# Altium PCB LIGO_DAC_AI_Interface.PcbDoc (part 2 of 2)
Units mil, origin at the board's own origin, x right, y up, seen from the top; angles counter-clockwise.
Board outline 2600 x 10000 mil, 6 copper layers (Top Layer, InternalPlane1, Mid-Layer 1, Mid-Layer 2, Internal Plane 2, Bottom Layer); 72 components, 113 nets, 425 pads, 169 vias.
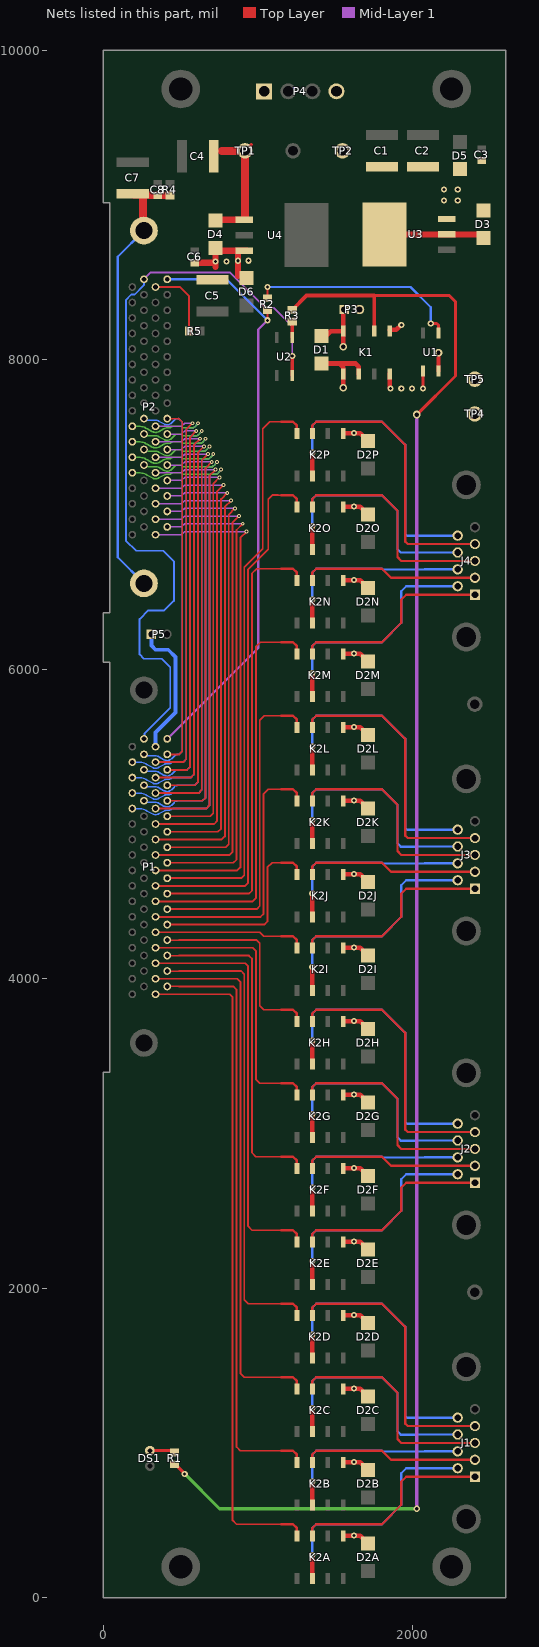
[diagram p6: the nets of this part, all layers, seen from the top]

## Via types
v1: diameter 40, hole 20, Top Layer to Bottom Layer, 134 vias
v2: diameter 25, hole 12, Top Layer to Bottom Layer, 30 vias
v3: diameter 50, hole 28, Top Layer to Bottom Layer, 5 vias

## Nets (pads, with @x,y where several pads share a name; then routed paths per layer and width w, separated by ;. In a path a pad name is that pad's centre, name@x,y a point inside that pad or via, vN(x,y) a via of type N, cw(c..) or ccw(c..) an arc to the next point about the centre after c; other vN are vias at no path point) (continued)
InputN25: P1.59 P2.43 | length 3357.4
  Mid-Layer 2 w8: v2@760,7287.52 v2(760,7290)
  Mid-Layer 2 w9: P2.43@186.81,7270 224.74,7270 226.94,7270 cw(c226.94,7164.19) 283.01,7253.92 283.21,7253.81 315.61,7236.08 ccw(c336.81,7270) 336.81,7230 ccw(c336.81,7270) 358.01,7236.08 390.61,7253.92 cw(c411.81,7220) 411.81,7260 424.74,7260 ccw(c424.74,7277.07) 436.81,7265 cw(c448.88,7252.93) 448.88,7270 486.81,7270 505,7270
  Mid-Layer 2 w10: 505,7270 515,7260 727.28,7260 ccw(c727.28,7270) 732.64,7261.55 735.28,7263.23 741.74,7268.19 ccw(c725,7290) 748.39,7275.54 cw(c756.89,7270.27) 749.79,7277.31 758.25,7285.77 ccw(c754.02,7290) v2(760,7290)
  Bottom Layer w8: v2@760,7287.52 v2(760,7290)
  Bottom Layer w9: P1.59@186.81,5100 224.74,5100 226.94,5100 cw(c226.94,4994.19) 283.01,5083.92 283.21,5083.81 315.61,5066.08 ccw(c336.81,5100) 336.81,5060 ccw(c336.81,5100) 358.01,5066.08 390.61,5083.92 cw(c411.81,5050) 411.81,5090 424.74,5090 ccw(c424.74,5107.07) 436.81,5095 cw(c448.88,5082.93) 448.88,5100
  Bottom Layer w10: 695,7260 727.28,7260 ccw(c727.28,7270) 732.64,7261.55 735.28,7263.23 741.74,7268.19 ccw(c725,7290) 748.39,7275.54 cw(c756.89,7270.27) 749.79,7277.31 758.25,7285.77 ccw(c754.02,7290) v2(760,7290)
  Bottom Layer w12: 448.88,5100 665,5100 685,5120 685,7246.81 ; 685,7250 695,7260
InputN26: P1.60 P2.44 | length 3166.4
  Mid-Layer 2 w8: v2@735,7337.52 v2(735,7340)
  Mid-Layer 2 w9: P2.44@261.81,7320 ccw(c285.95,7344.14) 285.95,7310 336.81,7310 cw(c336.81,7270) 358.01,7303.92 390.61,7286.08 ccw(c411.81,7320) 411.81,7280 ccw(c411.81,7320) 440.1,7291.72 440.1,7291.92 456.46,7308.28 cw(c484.74,7280) 484.74,7320 486.81,7320 505,7320
  Mid-Layer 2 w10: 505,7320 515,7310 702.28,7310 ccw(c702.28,7320) 707.64,7311.55 710.28,7313.23 716.74,7318.19 ccw(c700,7340) 723.39,7325.54 cw(c731.89,7320.27) 724.79,7327.31 733.25,7335.77 ccw(c729.02,7340) v2(735,7340)
  Bottom Layer w8: v2@735,7337.52 v2(735,7340)
  Bottom Layer w9: P1.60@261.81,5150 ccw(c285.95,5174.14) 285.95,5140 336.81,5140 cw(c336.81,5100) 358.01,5133.92 390.61,5116.08 ccw(c411.81,5150) 411.81,5110 ccw(c411.81,5150) 440.1,5121.72 440.1,5121.92 456.46,5138.28 cw(c484.74,5110) 484.74,5150
  Bottom Layer w10: 670,7310 702.28,7310 ccw(c702.28,7320) 707.64,7311.55 710.28,7313.23 716.74,7318.19 ccw(c700,7340) 723.39,7325.54 cw(c731.89,7320.27) 724.79,7327.31 733.25,7335.77 ccw(c729.02,7340) v2(735,7340)
  Bottom Layer w12: 484.74,5150 640,5150 660,5170 660,7296.81 ; 660,7300 670,7310
InputN27: P1.61 P2.45 | length 3257.4
  Mid-Layer 2 w8: v2@710,7387.52 v2(710,7390)
  Mid-Layer 2 w9: P2.45@186.81,7370 224.74,7370 226.94,7370 cw(c226.94,7264.19) 283.01,7353.92 283.21,7353.81 315.61,7336.08 ccw(c336.81,7370) 336.81,7330 ccw(c336.81,7370) 358.01,7336.08 390.61,7353.92 cw(c411.81,7320) 411.81,7360 424.74,7360 ccw(c424.74,7377.07) 436.81,7365 cw(c448.88,7352.93) 448.88,7370 486.81,7370 505,7370
  Mid-Layer 2 w10: 505,7370 515,7360 677.28,7360 ccw(c677.28,7370) 682.64,7361.55 685.28,7363.23 691.74,7368.19 ccw(c675,7390) 698.39,7375.54 cw(c706.89,7370.27) 699.79,7377.31 708.25,7385.77 ccw(c704.02,7390) v2(710,7390)
  Bottom Layer w8: v2@710,7387.52 v2(710,7390)
  Bottom Layer w9: P1.61@186.81,5200 224.74,5200 226.94,5200 cw(c226.94,5094.19) 283.01,5183.92 283.21,5183.81 315.61,5166.08 ccw(c336.81,5200) 336.81,5160 ccw(c336.81,5200) 358.01,5166.08 390.61,5183.92 cw(c411.81,5150) 411.81,5190 424.74,5190 ccw(c424.74,5207.07) 436.81,5195 cw(c448.88,5182.93) 448.88,5200
  Bottom Layer w10: 645,7360 677.28,7360 ccw(c677.28,7370) 682.64,7361.55 685.28,7363.23 691.74,7368.19 ccw(c675,7390) 698.39,7375.54 cw(c706.89,7370.27) 699.79,7377.31 708.25,7385.77 ccw(c704.02,7390) v2(710,7390)
  Bottom Layer w12: 448.88,5200 615,5200 635,5220 635,7346.81 ; 635,7350 645,7360
InputN28: P1.62 P2.46 | length 3066.4
  Mid-Layer 2 w8: v2@685,7437.52 v2(685,7440)
  Mid-Layer 2 w9: P2.46@261.81,7420 ccw(c285.95,7444.14) 285.95,7410 336.81,7410 cw(c336.81,7370) 358.01,7403.92 390.61,7386.08 ccw(c411.81,7420) 411.81,7380 ccw(c411.81,7420) 440.1,7391.72 440.1,7391.92 456.46,7408.28 cw(c484.74,7380) 484.74,7420 486.81,7420 505,7420
  Mid-Layer 2 w10: 505,7420 515,7410 652.28,7410 ccw(c652.28,7420) 657.64,7411.55 660.28,7413.23 666.74,7418.19 ccw(c650,7440) 673.39,7425.54 cw(c681.89,7420.27) 674.79,7427.31 683.25,7435.77 ccw(c679.02,7440) v2(685,7440)
  Bottom Layer w8: v2@685,7437.52 v2(685,7440)
  Bottom Layer w9: P1.62@261.81,5250 ccw(c285.95,5274.14) 285.95,5240 336.81,5240 cw(c336.81,5200) 358.01,5233.92 390.61,5216.08 ccw(c411.81,5250) 411.81,5210 ccw(c411.81,5250) 440.1,5221.72 440.1,5221.92 456.46,5238.28 cw(c484.74,5210) 484.74,5250
  Bottom Layer w10: 620,7410 652.28,7410 ccw(c652.28,7420) 657.64,7411.55 660.28,7413.23 666.74,7418.19 ccw(c650,7440) 673.39,7425.54 cw(c681.89,7420.27) 674.79,7427.31 683.25,7435.77 ccw(c679.02,7440) v2(685,7440)
  Bottom Layer w12: 484.74,5250 590,5250 610,5270 610,7396.81 ; 610,7400 620,7410
InputN29: P1.63 P2.47 | length 3157.4
  Mid-Layer 2 w8: v2@660,7487.52 v2(660,7490)
  Mid-Layer 2 w9: P2.47@186.81,7470 224.74,7470 226.94,7470 cw(c226.94,7364.19) 283.01,7453.92 283.21,7453.81 315.61,7436.08 ccw(c336.81,7470) 336.81,7430 ccw(c336.81,7470) 358.01,7436.08 390.61,7453.92 cw(c411.81,7420) 411.81,7460 424.74,7460 ccw(c424.74,7477.07) 436.81,7465 cw(c448.88,7452.93) 448.88,7470 486.81,7470 505,7470
  Mid-Layer 2 w10: 505,7470 515,7460 627.28,7460 ccw(c627.28,7470) 632.64,7461.55 635.28,7463.23 641.74,7468.19 ccw(c625,7490) 648.39,7475.54 cw(c656.89,7470.27) 649.79,7477.31 658.25,7485.77 ccw(c654.02,7490) v2(660,7490)
  Bottom Layer w8: v2@660,7487.52 v2(660,7490)
  Bottom Layer w9: P1.63@186.81,5300 224.74,5300 226.94,5300 cw(c226.94,5194.19) 283.01,5283.92 283.21,5283.81 315.61,5266.08 ccw(c336.81,5300) 336.81,5260 ccw(c336.81,5300) 358.01,5266.08 390.61,5283.92 cw(c411.81,5250) 411.81,5290 424.74,5290 ccw(c424.74,5307.07) 436.81,5295 cw(c448.88,5282.93) 448.88,5300
  Bottom Layer w10: 595,7460 627.28,7460 ccw(c627.28,7470) 632.64,7461.55 635.28,7463.23 641.74,7468.19 ccw(c625,7490) 648.39,7475.54 cw(c656.89,7470.27) 649.79,7477.31 658.25,7485.77 ccw(c654.02,7490) v2(660,7490)
  Bottom Layer w12: 448.88,5300 565,5300 585,5320 585,7446.81 ; 585,7450 595,7460
InputN30: P1.64 P2.48 | length 2969.6
  Mid-Layer 2 w8: v2@635,7537.52 v2(635,7540)
  Mid-Layer 2 w9: P2.48@261.81,7520 ccw(c285.95,7544.14) 285.95,7510 336.81,7510 cw(c336.81,7470) 358.01,7503.92 390.61,7486.08 ccw(c411.81,7520) 411.81,7480 ccw(c411.81,7520) 440.1,7491.72 440.1,7491.92 456.46,7508.28 cw(c484.74,7480) 484.74,7520 486.81,7520 505,7520
  Mid-Layer 2 w10: 505,7520 515,7510 602.28,7510 ccw(c602.28,7520) 607.64,7511.55 610.28,7513.23 616.74,7518.19 ccw(c600,7540) 623.39,7525.54 cw(c631.89,7520.27) 624.79,7527.31 633.25,7535.77 ccw(c629.02,7540) v2(635,7540)
  Bottom Layer w8: v2@635,7537.52 v2(635,7540)
  Bottom Layer w9: P1.64@261.81,5350 ccw(c285.95,5374.14) 285.95,5340 336.81,5340 cw(c336.81,5300) 358.01,5333.92 390.61,5316.08 ccw(c411.81,5350) 411.81,5310 ccw(c411.81,5350) 440.1,5321.72 440.1,5321.92 456.46,5338.28 cw(c484.74,5310) 484.74,5350
  Bottom Layer w10: 570,7510 602.28,7510 ccw(c602.28,7520) 607.64,7511.55 610.28,7513.23 616.74,7518.19 ccw(c600,7540) 623.39,7525.54 cw(c631.89,7520.27) 624.79,7527.31 633.25,7535.77 ccw(c629.02,7540) v2(635,7540)
  Bottom Layer w12: 484.74,5350 540,5350 560,5370 560,7500 570,7510
InputN31: P1.65 P2.49 | length 3083.2
  Mid-Layer 2 w8: v2@610,7587.52 v2(610,7590)
  Mid-Layer 2 w9: P2.49@186.81,7570 224.74,7570 226.94,7570 cw(c226.94,7464.19) 283.01,7553.92 283.21,7553.81 315.61,7536.08 ccw(c336.81,7570) 336.81,7530 ccw(c336.81,7570) 358.01,7536.08 390.61,7553.92 cw(c411.81,7520) 411.81,7560 424.74,7560 ccw(c424.74,7577.07) 436.81,7565 cw(c448.88,7552.93) 448.88,7570 486.81,7570 505,7570
  Mid-Layer 2 w10: 505,7570 515,7560 577.28,7560 ; 577.28,7560 ccw(c577.28,7570) 582.64,7561.55 ; 577.28,7560 ccw(c577.28,7570) 582.64,7561.55 ; 582.64,7561.55 585.28,7563.23 591.74,7568.19 ; 591.74,7568.19 ccw(c575,7590) 598.39,7575.54 ; 591.74,7568.19 ccw(c575,7590) 598.39,7575.54 ; 598.39,7575.54 cw(c606.89,7570.27) 599.79,7577.31 ; 598.39,7575.54 cw(c606.89,7570.27) 599.79,7577.31 ; 599.79,7577.31 v2@608.25,7585.77 ; v2@608.25,7585.77 ccw(c604.02,7590) v2(610,7590) cw(c604.02,7590) v2@608.25,7585.77
  Bottom Layer w8: v2@610,7587.52 v2(610,7590)
  Bottom Layer w9: P1.65@186.81,5400 224.74,5400 226.94,5400 cw(c226.94,5294.19) 283.01,5383.92 283.21,5383.81 315.61,5366.08 ccw(c336.81,5400) 336.81,5360 ccw(c336.81,5400) 358.01,5366.08 390.61,5383.92 cw(c411.81,5350) 411.81,5390 424.74,5390 ccw(c424.74,5407.07) 436.81,5395 cw(c448.88,5382.93) 448.88,5400
  Bottom Layer w10: 545,7560 577.28,7560 ccw(c577.28,7570) 582.64,7561.55 585.28,7563.23 591.74,7568.19 ccw(c575,7590) 598.39,7575.54 cw(c606.89,7570.27) 599.79,7577.31 608.25,7585.77 ccw(c604.02,7590) v2(610,7590)
  Bottom Layer w12: 448.88,5400 515,5400 535,5420 535,7550 545,7560
InputN32: P1.66 P2.50 | length 2682.6
  Bottom Layer w9: P1.66@261.81,5450 ccw(c285.95,5474.14) 285.95,5440 336.81,5440 cw(c336.81,5400) 358.01,5433.92 390.61,5416.08 ccw(c411.81,5450) 411.81,5410 ccw(c411.81,5450) 440.1,5421.72 440.1,5421.92 456.46,5438.28 cw(c484.74,5410) 484.74,5450 486.81,5450 ; P2.50@261.81,7620 ccw(c285.95,7644.14) 285.95,7610 336.81,7610 cw(c336.81,7570) 358.01,7603.92 390.61,7586.08 ccw(c411.81,7620) 411.81,7580 ccw(c411.81,7620) 440.1,7591.72 440.1,7591.92 456.46,7608.28 cw(c484.74,7580) 484.74,7620 486.81,7620
  Bottom Layer w12: 486.81,7620 509,7597.81 509,5469 490,5450
InputP1: K2A.4 P1.1 | length 4372.2
  Top Layer w9: P1.1@336.81,3900 486.81,3900
  Top Layer w12: 486.81,3900 815,3900 835,3880 835,500 860,475 1130,475 1150,475
  Top Layer w15: 1150,475 1225,475 1250,450 K2A.4@1250,400
InputP2: K2B.4 P1.2 | length 3872.2
  Top Layer w9: P1.2@411.81,3950 486.81,3950
  Top Layer w12: 486.81,3950 840,3950 860,3930 860,975 885,950 1130,950 1150,950
  Top Layer w15: 1150,950 1225,950 1250,925 K2B.4@1250,875
InputP3: K2C.4 P1.3 | length 3522.2
  Top Layer w9: P1.3@336.81,4000 486.81,4000
  Top Layer w12: 486.81,4000 865,4000 885,3980 885,1450 910,1425 1130,1425 1150,1425
  Top Layer w15: 1150,1425 1225,1425 1250,1400 K2C.4@1250,1350
InputP4: K2D.4 P1.4 | length 3022.2
  Top Layer w9: P1.4@411.81,4050 486.81,4050
  Top Layer w12: 486.81,4050 890,4050 910,4030 910,1925 935,1900 1130,1900 1150,1900
  Top Layer w15: 1150,1900 1225,1900 1250,1875 K2D.4@1250,1825
InputP5: K2E.4 P1.5 | length 2672.2
  Top Layer w9: P1.5@336.81,4100 486.81,4100
  Top Layer w12: 486.81,4100 915,4100 935,4080 935,2400 960,2375 1130,2375 1150,2375
  Top Layer w15: 1150,2375 1225,2375 1250,2350 K2E.4@1250,2300
InputP6: K2F.4 P1.6 | length 2172.2
  Top Layer w9: P1.6@411.81,4150 486.81,4150
  Top Layer w12: 486.81,4150 940,4150 960,4130 960,2875 985,2850 1130,2850 1150,2850
  Top Layer w15: 1150,2850 1225,2850 1250,2825 K2F.4@1250,2775
InputP7: K2G.4 P1.7 | length 1822.2
  Top Layer w9: P1.7@336.81,4200 486.81,4200
  Top Layer w12: 486.81,4200 965,4200 985,4180 985,3350 1010,3325 1130,3325 1150,3325
  Top Layer w15: 1150,3325 1225,3325 1250,3300 K2G.4@1250,3250
InputP8: K2H.4 P1.8 | length 1322.2
  Top Layer w9: P1.8@411.81,4250 486.81,4250
  Top Layer w12: 486.81,4250 990,4250 1010,4230 1010,3825 1035,3800 1130,3800 1150,3800
  Top Layer w15: 1150,3800 1225,3800 1250,3775 K2H.4@1250,3725
InputP9: K2I.4 P1.9 | length 983.9
  Top Layer w12: P1.9@336.81,4300 1010,4300 1035,4275 1130,4275 1150,4275
  Top Layer w15: 1150,4275 1225,4275 1250,4250 K2I.4@1250,4200
InputP10: K2J.4 P1.10 | length 1269.3
  Top Layer w12: P1.10@411.81,4350 1040,4350 1060,4370 1060,4720 1090,4750 1130,4750 1150,4750
  Top Layer w15: 1150,4750 1225,4750 1250,4725 K2J.4@1250,4675
InputP11: K2K.4 P1.11 | length 1769.3
  Top Layer w12: P1.11@336.81,4400 1015,4400 1035,4420 1035,5195 1065,5225 1130,5225 1150,5225
  Top Layer w15: 1150,5225 1225,5225 1250,5200 K2K.4@1250,5150
InputP12: K2L.4 P1.12 | length 2119.3
  Top Layer w12: P1.12@411.81,4450 990,4450 1010,4470 1010,5670 1040,5700 1130,5700 1150,5700
  Top Layer w15: 1150,5700 1225,5700 1250,5675 K2L.4@1250,5625
InputP13: K2M.4 P1.13 | length 2619.3
  Top Layer w12: P1.13@336.81,4500 965,4500 985,4520 985,6145 1015,6175 1130,6175 1150,6175
  Top Layer w15: 1150,6175 1225,6175 1250,6150 K2M.4@1250,6100
InputP14: K2N.4 P1.14 | length 2969.3
  Top Layer w12: P1.14@411.81,4550 940,4550 960,4570 960,6620 990,6650 1130,6650 1150,6650
  Top Layer w15: 1150,6650 1225,6650 1250,6625 K2N.4@1250,6575
InputP15: K2O.4 P1.15 | length 3396.4
  Top Layer w12: P1.15@336.81,4600 915,4600 935,4620 935,6645 1065,6775 1065,7100 1090.79,7125.79 1130,7125.79 1150,7125
  Top Layer w15: 1150,7125 1225,7125 1250,7100 K2O.4@1250,7050
InputP16: K2P.4 P1.16 | length 3740.2
  Top Layer w12: P1.16@411.81,4650 890,4650 910,4670 910,6660 1030,6780 1030,7555 1075,7600 1130,7600 1150,7600
  Top Layer w15: 1150,7600 1225,7600 1250,7575 K2P.4@1250,7525
InputP17: P1.17 P2.1 | length 3336.3
  Top Layer w12: P1.17@336.81,4700 865,4700 885,4720 885,6846.81 ; 885,6850 v2(925,6890)
  Mid-Layer 1 w9: P2.1@336.81,6870 486.81,6870 505,6870
  Mid-Layer 1 w10: 505,6870 525,6890 v2(925,6890)
InputP18: P1.18 P2.2 | length 3136.3
  Top Layer w12: P1.18@411.81,4750 840,4750 860,4770 860,6896.81 ; 860,6900 v2(900,6940)
  Mid-Layer 1 w9: P2.2@411.81,6920 486.81,6920 505,6920
  Mid-Layer 1 w10: 505,6920 525,6940 v2(900,6940)
InputP19: P1.19 P2.3 | length 3236.3
  Top Layer w12: P1.19@336.81,4800 815,4800 835,4820 835,6946.81 ; 835,6950 v2(875,6990)
  Mid-Layer 1 w9: P2.3@336.81,6970 486.81,6970 505,6970
  Mid-Layer 1 w10: 505,6970 525,6990 v2(875,6990)
InputP20: P1.20 P2.4 | length 3036.3
  Top Layer w12: P1.20@411.81,4850 790,4850 810,4870 810,6996.81 ; 810,7000 v2(850,7040)
  Mid-Layer 1 w9: P2.4@411.81,7020 486.81,7020 505,7020
  Mid-Layer 1 w10: 505,7020 525,7040 v2(850,7040)
InputP21: P1.21 P2.5 | length 3136.3
  Top Layer w12: P1.21@336.81,4900 765,4900 785,4920 785,7046.81 ; 785,7050 v2(825,7090)
  Mid-Layer 1 w9: P2.5@336.81,7070 486.81,7070 505,7070
  Mid-Layer 1 w10: 505,7070 525,7090 v2(825,7090)
InputP22: P1.22 P2.6 | length 2936.3
  Top Layer w12: P1.22@411.81,4950 740,4950 760,4970 760,7096.81 ; 760,7100 v2(800,7140)
  Mid-Layer 1 w9: P2.6@411.81,7120 486.81,7120 505,7120
  Mid-Layer 1 w10: 505,7120 525,7140 v2(800,7140)
InputP23: P1.23 P2.7 | length 3036.3
  Top Layer w12: P1.23@336.81,5000 715,5000 735,5020 735,7146.81 ; 735,7150 v2(775,7190)
  Mid-Layer 1 w9: P2.7@336.81,7170 486.81,7170 505,7170
  Mid-Layer 1 w10: 505,7170 525,7190 v2(775,7190)
InputP24: P1.24 P2.8 | length 2836.3
  Top Layer w12: P1.24@411.81,5050 690,5050 710,5070 710,7196.81 ; 710,7200 v2(750,7240)
  Mid-Layer 1 w9: P2.8@411.81,7220 486.81,7220 505,7220
  Mid-Layer 1 w10: 505,7220 525,7240 v2(750,7240)
InputP25: P1.25 P2.9 | length 2936.3
  Top Layer w12: P1.25@336.81,5100 665,5100 685,5120 685,7246.81 ; 685,7250 v2(725,7290)
  Mid-Layer 1 w9: P2.9@336.81,7270 486.81,7270 505,7270
  Mid-Layer 1 w10: 505,7270 525,7290 v2(725,7290)
InputP26: P1.26 P2.10 | length 2736.3
  Top Layer w12: P1.26@411.81,5150 640,5150 660,5170 660,7296.81 ; 660,7300 v2(700,7340)
  Mid-Layer 1 w9: P2.10@411.81,7320 486.81,7320 505,7320
  Mid-Layer 1 w10: 505,7320 525,7340 v2(700,7340)
InputP27: P1.27 P2.11 | length 2836.3
  Top Layer w12: P1.27@336.81,5200 615,5200 635,5220 635,7346.81 ; 635,7350 v2(675,7390)
  Mid-Layer 1 w9: P2.11@336.81,7370 486.81,7370 505,7370
  Mid-Layer 1 w10: 505,7370 525,7390 v2(675,7390)
InputP28: P1.28 P2.12 | length 2636.3
  Top Layer w12: P1.28@411.81,5250 590,5250 610,5270 610,7396.81 ; 610,7400 v2(650,7440)
  Mid-Layer 1 w9: P2.12@411.81,7420 486.81,7420 505,7420
  Mid-Layer 1 w10: 505,7420 525,7440 v2(650,7440)
InputP29: P1.29 P2.13 | length 2736.3
  Top Layer w12: P1.29@336.81,5300 565,5300 585,5320 585,7446.81 ; 585,7450 v2(625,7490)
  Mid-Layer 1 w9: P2.13@336.81,7470 486.81,7470 505,7470
  Mid-Layer 1 w10: 505,7470 525,7490 v2(625,7490)
InputP30: P1.30 P2.14 | length 2539.5
  Top Layer w12: P1.30@411.81,5350 540,5350 560,5370 560,7500 v2(600,7540)
  Mid-Layer 1 w9: P2.14@411.81,7520 486.81,7520 505,7520
  Mid-Layer 1 w10: 505,7520 525,7540 v2(600,7540)
InputP31: P1.31 P2.15 | length 2639.5
  Top Layer w12: P1.31@336.81,5400 515,5400 535,5420 535,7550 v2(575,7590)
  Mid-Layer 1 w9: P2.15@336.81,7570 486.81,7570 505,7570
  Mid-Layer 1 w10: 505,7570 525,7590 v2(575,7590)
InputP32: P1.32 P2.16 | length 2340.3
  Top Layer w9: P2.16@411.81,7620 486.81,7620
  Top Layer w12: P1.32@411.81,5450 490,5450 509,5469 509,7597.81 486.81,7620
InputRTN: P1.33 P5.1 | length 891.8
  Bottom Layer w25: P5.1@310,6226.5 310,6153 337,6126 419,6126 465,6080 465,5720 336.81,5591.81 P1.33@336.81,5500
NetC7_2: C7.2 C8.2 P2.69 P2.70 R4.1 | length 2869.6
  Top Layer w25: P2.70@255,8841.77 P2.70@261.81,8834.96
  Top Layer w50: C7.2@196.5,9066.14 255,9066.14 295.08,9066.14 298.62,9062.6 345,9062.6 R4.1@425,9062.6 ; P2.70@255,8841.77 C7.2@255,9051.54
  Bottom Layer w15: P2.69@261.81,6555.04 92.5,6724.35 92.5,8665.65 P2.70@261.81,8834.96
NetD1_1: D1.1 K1.8 P3.1 U1.4 | length 496
  Top Layer w25: U1.4@2165,7926.97 v3(2165,8045)
  Top Layer w30: D1.1@1410,8153.58 1438.58,8153.58 1470,8185 K1.8@1550,8185 ; v3(1550,8085) K1.8@1550,8185 ; P3.1@1550,8310 K1.8@1550,8185
NetDS1_2: DS1.2 R1.1 | length 154.9
  Top Layer w20: DS1.2@300,950 R1.1@454.88,950
NetK1_6: K1.6 R1.2 R3.2 | length 10928.5
  Top Layer w20: R1.2@460,862.6 463.94,862.6 479.53,847.01 479.53,845.47 v1(525,800) ; K1.6@1750,8185 1750,8415 2235,8415 2275,8375 2275,7895.71 v3(2025.09,7645.8)
  Top Layer w25: R3.2@1220,8322.4 1312.6,8415 1750,8415
  Mid-Layer 1 w20: v1@2025.09,575 v3(2025.09,7645.8)
  Mid-Layer 2 w20: v1(525,800) 750,575 v1(2025,575)
NetP2_33: P2.33 R5.1 | length 467
  Top Layer w12: P2.33@336.81,8469.81 495.19,8469.81 552.6,8412.4 R5.1@552.6,8185
NetR2_2: R2.2 U1.1 | length 1391.6
  Top Layer w15: R2.2@1060,8397.4 v1(1060,8470)
  Top Layer w20: v1(2115,8235) 2153.28,8235 2165,8223.28 U1.1@2165,8173.03
  Bottom Layer w15: v1(1060,8470) 1985,8470 2115,8340 v1(2115,8235)
NetR3_1: R3.1 U2.1 | length 104.6
  Top Layer w25: U2.1@1220,8143.03 R3.1@1220,8247.6
OutputN1: J1.6 K2A.6 | length 1544
  Top Layer w30: K2A.6@1350,124.41 v1(1350,275)
  Bottom Layer w15: v1(1350,275) 1350,450 1375,475 1800,475 1925,600 1925,804 1956.89,835.89 2025,835.89 2075,836.42 J1.6@2289.09,836.42
OutputN2: J1.7 K2B.6 | length 1277.1
  Top Layer w30: K2B.6@1350,599.41 v1(1350,750)
  Bottom Layer w15: v1(1350,750) 1350,925 1375,950 1800,950 1805.05,944.95 2025,944.95 2075,945.47 J1.7@2289.09,945.47
OutputN3: J1.8 K2C.6 | length 1575.2
  Top Layer w30: K2C.6@1350,1074.41 v1(1350,1225)
  Bottom Layer w15: v1(1350,1225) 1350,1400 1375,1425 1800,1425 1900,1325 1900,1075 1921,1054 2025,1054 2075,1054.53 J1.8@2289.09,1054.53
OutputN4: J1.9 K2D.6 | length 1917.1
  Top Layer w30: K2D.6@1350,1549.41 v1(1350,1700)
  Bottom Layer w15: v1(1350,1700) 1350,1875 1375,1900 1800,1900 1950,1750 1950,1175 1961.94,1163.06 2025,1163.06 2075,1163.58 J1.9@2289.09,1163.58
OutputN5: J2.6 K2E.6 | length 1544
  Top Layer w30: K2E.6@1350,2024.41 v1(1350,2175)
  Bottom Layer w15: v1(1350,2175) 1350,2350 1375,2375 1800,2375 1925,2500 1925,2704 1956.89,2735.89 2025,2735.89 2075,2736.42 J2.6@2289.09,2736.42
OutputN6: J2.7 K2F.6 | length 1277.1
  Top Layer w30: K2F.6@1350,2499.41 v1(1350,2650)
  Bottom Layer w15: v1(1350,2650) 1350,2825 1375,2850 1800,2850 1805.05,2844.95 2025,2844.95 2075,2845.47 J2.7@2289.09,2845.47
OutputN7: J2.8 K2G.6 | length 1575.2
  Top Layer w30: K2G.6@1350,2974.41 v1(1350,3125)
  Bottom Layer w15: v1(1350,3125) 1350,3300 1375,3325 1800,3325 1900,3225 1900,2975 1921,2954 2025,2954 2075,2954.53 J2.8@2289.09,2954.53
OutputN8: J2.9 K2H.6 | length 1917.1
  Top Layer w30: K2H.6@1350,3449.41 v1(1350,3600)
  Bottom Layer w15: v1(1350,3600) 1350,3775 1375,3800 1800,3800 1950,3650 1950,3075 1961.94,3063.06 2025,3063.06 2075,3063.58 J2.9@2289.09,3063.58
OutputN9: J3.6 K2I.6 | length 1544
  Top Layer w30: K2I.6@1350,3924.41 v1(1350,4075)
  Bottom Layer w15: v1(1350,4075) 1350,4250 1375,4275 1800,4275 1925,4400 1925,4604 1956.89,4635.89 2025,4635.89 2075,4636.42 J3.6@2289.09,4636.42
OutputN10: J3.7 K2J.6 | length 1277.1
  Top Layer w30: K2J.6@1350,4399.41 v1(1350,4550)
  Bottom Layer w15: v1(1350,4550) 1350,4725 1375,4750 1800,4750 1805.05,4744.95 2025,4744.95 2075,4745.47 J3.7@2289.09,4745.47
OutputN11: J3.8 K2K.6 | length 1575.2
  Top Layer w30: K2K.6@1350,4874.41 v1(1350,5025)
  Bottom Layer w15: v1(1350,5025) 1350,5200 1375,5225 1800,5225 1900,5125 1900,4875 1921,4854 2025,4854 2075,4854.53 J3.8@2289.09,4854.53
OutputN12: J3.9 K2L.6 | length 1917.1
  Top Layer w30: K2L.6@1350,5349.41 v1(1350,5500)
  Bottom Layer w15: v1(1350,5500) 1350,5675 1375,5700 1800,5700 1950,5550 1950,4975 1961.94,4963.06 2025,4963.06 2075,4963.58 J3.9@2289.09,4963.58
OutputN13: J4.6 K2M.6 | length 1544
  Top Layer w30: K2M.6@1350,5824.41 v1(1350,5975)
  Bottom Layer w15: v1(1350,5975) 1350,6150 1375,6175 1800,6175 1925,6300 1925,6504 1956.89,6535.89 2025,6535.89 2075,6536.42 J4.6@2289.09,6536.42
OutputN14: J4.7 K2N.6 | length 1277.1
  Top Layer w30: K2N.6@1350,6299.41 v1(1350,6450)
  Bottom Layer w15: v1(1350,6450) 1350,6625 1375,6650 1800,6650 1805.05,6644.95 2025,6644.95 2075,6645.47 J4.7@2289.09,6645.47
OutputN15: J4.8 K2O.6 | length 1575.2
  Top Layer w30: K2O.6@1350,6774.41 v1(1350,6925)
  Bottom Layer w15: v1(1350,6925) 1350,7100 1375,7125 1800,7125 1900,7025 1900,6775 1921,6754 2025,6754 2075,6754.53 J4.8@2289.09,6754.53
OutputN16: J4.9 K2P.6 | length 1917.1
  Top Layer w30: K2P.6@1350,7249.41 v1(1350,7400)
  Bottom Layer w15: v1(1350,7400) 1350,7575 1375,7600 1800,7600 1950,7450 1950,6875 1961.94,6863.06 2025,6863.06 2075,6863.58 J4.9@2289.09,6863.58
OutputP1: J1.1 K2A.3 | length 1326.2
  Top Layer w15: K2A.3@1350,400 1350,450 1375,475 1800,475 1925,600 1925,750 1956.89,781.89 2025,781.89 2075,781.89 J1.1@2400.91,781.89
OutputP2: J1.2 K2B.3 | length 1135.7
  Top Layer w15: K2B.3@1350,875 1350,925 1375,950 1800,950 1859.05,890.95 2025,890.95 2075,890.94 J1.2@2400.91,890.94
OutputP3: J1.3 K2C.3 | length 1463
  Top Layer w15: K2C.3@1350,1350 1350,1400 1375,1425 1800,1425 1900,1325 1900,1025 1925,1000 2025,1000 2075,1000 J1.3@2400.91,1000
OutputP4: J1.4 K2D.3 | length 1805
  Top Layer w15: K2D.3@1350,1825 1350,1875 1375,1900 1800,1900 1950,1750 1950,1125 1965.95,1109.05 2018.11,1109.05 2075,1109.06 J1.4@2400.91,1109.06
OutputP5: J2.1 K2E.3 | length 1326.2
  Top Layer w15: K2E.3@1350,2300 1350,2350 1375,2375 1800,2375 1925,2500 1925,2650 1956.89,2681.89 2025,2681.89 2075,2681.89 J2.1@2400.91,2681.89
OutputP6: J2.2 K2F.3 | length 1135.7
  Top Layer w15: K2F.3@1350,2775 1350,2825 1375,2850 1800,2850 1859.05,2790.95 2025,2790.95 2075,2790.94 J2.2@2400.91,2790.94
OutputP7: J2.3 K2G.3 | length 1463
  Top Layer w15: K2G.3@1350,3250 1350,3300 1375,3325 1800,3325 1900,3225 1900,2925 1925,2900 2025,2900 2075,2900 J2.3@2400.91,2900
OutputP8: J2.4 K2H.3 | length 1805
  Top Layer w15: K2H.3@1350,3725 1350,3775 1375,3800 1800,3800 1950,3650 1950,3025 1965.95,3009.05 2018.11,3009.05 2075,3009.06 J2.4@2400.91,3009.06
OutputP9: J3.1 K2I.3 | length 1326.2
  Top Layer w15: K2I.3@1350,4200 1350,4250 1375,4275 1800,4275 1925,4400 1925,4550 1956.89,4581.89 2025,4581.89 2075,4581.89 J3.1@2400.91,4581.89
OutputP10: J3.2 K2J.3 | length 1135.7
  Top Layer w15: K2J.3@1350,4675 1350,4725 1375,4750 1800,4750 1859.05,4690.95 2025,4690.95 2075,4690.94 J3.2@2400.91,4690.94
OutputP11: J3.3 K2K.3 | length 1463
  Top Layer w15: K2K.3@1350,5150 1350,5200 1375,5225 1800,5225 1900,5125 1900,4825 1925,4800 2025,4800 2075,4800 J3.3@2400.91,4800
OutputP12: J3.4 K2L.3 | length 1805
  Top Layer w15: K2L.3@1350,5625 1350,5675 1375,5700 1800,5700 1950,5550 1950,4925 1965.95,4909.06 2018.11,4909.06 2075,4909.06 J3.4@2400.91,4909.06
OutputP13: J4.1 K2M.3 | length 1326.2
  Top Layer w15: K2M.3@1350,6100 1350,6150 1375,6175 1800,6175 1925,6300 1925,6450 1956.89,6481.89 2025,6481.89 2075,6481.89 J4.1@2400.91,6481.89
OutputP14: J4.2 K2N.3 | length 1135.7
  Top Layer w15: K2N.3@1350,6575 1350,6625 1375,6650 1800,6650 1859.05,6590.95 2025,6590.95 2075,6590.94 J4.2@2400.91,6590.94
OutputP15: J4.3 K2O.3 | length 1463
  Top Layer w15: K2O.3@1350,7050 1350,7100 1375,7125 1800,7125 1900,7025 1900,6725 1925,6700 2025,6700 2075,6700 J4.3@2400.91,6700
OutputP16: J4.4 K2P.3 | length 1805
  Top Layer w15: K2P.3@1350,7525 1350,7575 1375,7600 1800,7600 1950,7450 1950,6825 1965.95,6809.06 2018.11,6809.06 2075,6809.06 J4.4@2400.91,6809.06
V+: C5.2 C6.2 D1.2 D2A.2 D2B.2 D2C.2 D2D.2 D2E.2 D2F.2 D2G.2 D2H.2 D2I.2 D2J.2 D2K.2 D2L.2 D2M.2 D2N.2 D2O.2 D2P.2 D4.1 D6.2 K1.1 K1.2 K1.5 K2A.1 K2B.1 K2C.1 K2D.1 K2E.1 K2F.1 K2G.1 K2H.1 K2I.1 K2J.1 K2K.1 K2L.1 K2M.1 K2N.1 K2O.1 K2P.1 TP4.1 U4.3 | length 4130.4
  Top Layer w20: D4.1@725,8716.42 D4.1@736.42,8705
  Top Layer w30: D1.2@1410,7976.42 1525,7976.42 ; K2A.1@1550,400 1660.79,400 D2A.2@1710,350.79 ; K2B.1@1550,875 1660.79,875 D2B.2@1710,825.79 ; K2C.1@1550,1350 1660.79,1350 D2C.2@1710,1300.79 ; K2D.1@1550,1825 1660.79,1825 D2D.2@1710,1775.79 ; K2E.1@1550,2300 1660.79,2300 D2E.2@1710,2250.79 ; K2F.1@1550,2775 1660.79,2775 D2F.2@1710,2725.79 ; K2G.1@1550,3250 1660.79,3250 D2G.2@1710,3200.79 ; K2H.1@1550,3725 1660.79,3725 D2H.2@1710,3675.79 ; K2I.1@1550,4200 1660.79,4200 D2I.2@1710,4150.79 ; K2J.1@1550,4675 1660.79,4675 D2J.2@1710,4625.79 ; K2K.1@1550,5150 1660.79,5150 D2K.2@1710,5100.79 ; K2L.1@1550,5625 1660.79,5625 D2L.2@1710,5575.79 ; K2M.1@1550,6100 1660.79,6100 D2M.2@1710,6050.79 ; K2N.1@1550,6575 1660.79,6575 D2N.2@1710,6525.79 ; K2O.1@1550,7050 1660.79,7050 D2O.2@1710,7000.79 ; K2P.1@1550,7525 1660.79,7525 D2P.2@1710,7475.79 ; v3(1550,7820) K1.1@1550,7909.41 1550,7951.42 1525,7976.42 ; K1.2@1650,7905 K1.2@1650,7909.41 1650,7955 1628.58,7976.42 1525,7976.42 ; K1.5@1850,8190 1850,8192.43 1850.75,8193.17 1893.17,8193.17 v1(1925,8225)
  Top Layer w40: C6.2@590,8626.61 716.61,8626.61 v1(725,8635) ; 725,8600.12 v1(725,8635) ; D4.1@725,8716.42 v1(725,8635) ; D4.1@736.42,8705 U4.3@870,8705 ; 870,8543.58 U4.3@870,8705 ; v1(870,8640) U4.3@870,8705 ; U4.3@926.81,8705 U4.3@910.91,8705 U4.3@870,8705
  other v1: 1620,402.2 1620,877.2 1620,1352.2 1620,1827.2 1620,2302.2 1620,2777.2 1620,3252.2 1620,3727.2 1620,4202.2 1620,4677.2 1620,5152.2 1620,5627.2 1620,6102.2 1620,6577.2 1620,7052.2 1620,7527.2 795,8635 938.42,8640.37
V-: C2.2 C3.2 D3.2 D5.1 K1.4 P3.2 TP5.1 U1.3 U3.3 | length 211
  Top Layer w20: v1(2065,7815) U1.3@2065,7926.97
  Top Layer w30: K1.4@1850,7911.97 1850,7820 v1(1855,7815)
  other v1: 1925,7815 1995,7815 2200,9030 2290,9030 2200,9100 2290,9100
VIN+: C4.2 D4.2 P4.1 TP1.1 U4.1 | length 830.2
  Top Layer w20: TP1.1@915,9350 955,9390
  Top Layer w40: D4.2@736.42,8905 U4.1@926.81,8905
  Top Layer w50: 765,9350 TP1.1@915,9350 U4.1@915,8916.81
Vin-: C1.2 D3.1 P4.4 TP2.1 U3.2 U3.4 | length 652.5
  Top Layer w40: U3.4@1817.52,8810 U3.2@2219.09,8810 D3.1@2470,8810
WD: P1.34 P2.34 R2.1 | length 3799
  Top Layer w12: v1(1060,8255) R2.1@1060,8322.6
  Mid-Layer 1 w15: P1.34@411.81,5550 1000,6138.19 1000,8195 v1(1060,8255)
  Bottom Layer w15: P2.34@411.81,8520 795,8520 v1(1060,8255)
WDM: P1.68 P2.68 U2.4 | length 5072.8
  Top Layer w25: U2.4@1220,7896.97 v1(1220,8025)
  Mid-Layer 1 w12: P2.68@261.81,8520 306.81,8565 815,8565 1045,8335 1100,8335 1220,8215 v1(1220,8025)
  Bottom Layer w12: P1.68@261.81,5550 264.31,5552.5 264.31,5584.31 432,5752 432,6013 377,6068 262,6068 234,6096 234,6324 290,6380 393,6380 455,6442 455,6697 386,6766 210.77,6766 145,6831.77 145,8386.17 180.83,8422 201,8422 261.81,8482.81 P2.68@261.81,8520
pads on no net: J1.5 J1.10 J1.11 J2.5 J2.10 J2.11 J3.5 J3.10 J3.11 J4.5 J4.10 J4.11 K1.7 P2.17 P2.18 P2.19 P2.20 P2.21 P2.22 P2.23 P2.24 P2.25 P2.26 P2.27 P2.28 P2.29 P2.30 P2.31 P2.32 P2.51 P2.52 P2.53 P2.54 P2.55 P2.56 P2.57 P2.58 P2.59 P2.60 P2.61 P2.62 P2.63 P2.64 P2.65 P2.66

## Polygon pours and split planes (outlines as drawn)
V+ on InternalPlane1 (split plane): 2579.9,20.1 20.1,20.1 20.1,3374.9 40,3374.9 43.92,3375.29 47.69,3376.43 51.17,3378.29 54.21,3380.79 56.71,3383.83 58.57,3387.31 59.71,3391.08 60.1,3395 60.1,6045 59.71,6048.92 58.57,6052.69 56.71,6056.17 54.21,6059.21 51.17,6061.71 47.69,6063.57 43.92,6064.71 40,6065.1 20.1,6065.1 20.1,6344.9 40,6344.9 43.92,6345.29 47.69,6346.43 51.17,6348.29 54.21,6350.79 56.71,6353.83 58.57,6357.31 59.71,6361.08 60.1,6365 60.1,9015 59.71,9018.92 58.57,9022.69 56.71,9026.17 54.21,9029.21 51.17,9031.71 47.69,9033.57 43.92,9034.71 40,9035.1 20.1,9035.1 20.1,9979.9 2579.9,9979.9
GND on Internal Plane 2 (split plane): 2579.9,20.1 20.1,20.1 20.1,3374.9 40,3374.9 43.92,3375.29 47.69,3376.43 51.17,3378.29 54.21,3380.79 56.71,3383.83 58.57,3387.31 59.71,3391.08 60.1,3395 60.1,6045 59.71,6048.92 58.57,6052.69 56.71,6056.17 54.21,6059.21 51.17,6061.71 47.69,6063.57 43.92,6064.71 40,6065.1 20.1,6065.1 20.1,6344.9 40,6344.9 43.92,6345.29 47.69,6346.43 51.17,6348.29 54.21,6350.79 56.71,6353.83 58.57,6357.31 59.71,6361.08 60.1,6365 60.1,9015 59.71,9018.92 58.57,9022.69 56.71,9026.17 54.21,9029.21 51.17,9031.71 47.69,9033.57 43.92,9034.71 40,9035.1 20.1,9035.1 20.1,9979.9 2579.9,9979.9

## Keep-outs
Keep-Out Layer:
  lines w10: 50,50 50,3350 75,3350 75,6075 50,6075 50,6325 70,6325 70,9050 50,9050 50,9950 2550,9950 2550,50 50,50
  lines w20: 0,0 0,10000 2600,10000 2600,0 0,0

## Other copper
Top Layer:
  rectangle net V-: 2160,8885 2500,9280
  rectangle net GND: 1693.13,9419.24 2490,9555
  rectangle net GND: 85,9245 365,9420
  rectangle net GND: 325,9115 548.73,9420
  rectangle net GND: 600,8155 970,8363.39
  rectangle net V+: 655,8485 1000,8728.39
  region net GND: 2460,8523.33 2460,8655 2254.94,8655 2254.94,8523.33
  rectangle net GND: 2163.33,8523.33 2335,8730.06
  rectangle net V-: 1825,7785 2095,7945
  rectangle net VIN+: 680,8885 1000,9525
  rectangle net VIN+: 903.22,9290.91 1103.22,9790
  rectangle net Vin-: 1455,9300 1655,9790
  rectangle net V-: 1955,9145 2330,9280
  rectangle net Vin-: 1455,9180 1655,9410
  rectangle net Vin-: 1580,9085 1905,9280
  region net Vin-: 2025,9105 1580,9105 1580,8515 2025,8515
  rectangle net GND: 1105,8510 1550,9100
Mid-Layer 1:
  region net V-: 2500,7785 2500,8465 2275,8465 2275,7785
  rectangle net NetD1_1: 1498.34,7989.65 2223.34,8149.65
  rectangle net V-: 1825,7785 2500,7945
  region net DAC1ENABLE: 1800,7600 1800,7900 1675,7900 1675,7600
  rectangle net DAC1ENABLE: 1675,7600 1925,7750
  region net DAC1ENABLE: 1925.11,100 1925.11,7692.75 1765.11,7692.75 1765.11,100
  rectangle net V-: 1605,8275 2500,8465
  region net V-: 2335,8335 2335,9145 2160,9145 2160,8335

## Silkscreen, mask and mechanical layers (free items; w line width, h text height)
Top Overlay:
  region: 825,1845 825,3140 465.19,3140 465.19,1845
  lines w20: 470.5,6226.5 510.5,6226.5 618,6334 763,6334
  text "WD Override" at 1730,8305 h45
  text "CH 13-16" at 2050,6575 h100 r90
  text "DAC RTN to GND Connection" at 668,6369 h75 r90
  text "Jumper Nominally Installed" at 753,6369 h75 r90
  text "CH 9-12" at 2050,4750 h100 r90
  text "CH 5-8" at 2050,2925 h100 r90
  text "S/N" at 820,1715 h75 r90
  text "REV: 1" at 525,1620 h75 r90
  text "LIGO DAC AI Interface" at 287,1617 h150 r90
  text "D2400023" at 412,1617 h125 r90
  text "CH 1-4" at 2050,1050 h100 r90
Mechanical 1:
  the board outline again, w20
Drill Drawing:
  circle w10: c3376.67,88.12 r33.33
  circle w10: c3826.67,88.12 r20
  circle w10: c3826.67,88.12 r33.33
  lines w10: 3043.33,54.79 3060,54.79 3076.67,71.46 3093.33,54.79 3110,54.79 3110,71.46 3093.33,88.12 3110,104.79 3110,121.46 3093.33,121.46 3076.67,104.79 3060,121.46 3043.33,121.46 3043.33,104.79 3060,88.12 3043.33,71.46 3043.33,54.79 ; 3193.33,54.79 3210,88.12 3193.33,121.46 3226.67,104.79 3260,121.46 3243.33,88.12 3260,54.79 3226.67,71.46 3193.33,54.79 ; 3206.67,68.12 3216.67,88.12 3206.67,108.12 3226.67,98.12 3246.67,108.12 3236.67,88.12 3246.67,68.12 3226.67,78.12 3206.67,68.12 ; 3493.33,54.79 3510,88.12 3493.33,121.46 3526.67,104.79 3560,121.46 3543.33,88.12 3560,54.79 3526.67,71.46 3493.33,54.79 ; 3643.33,54.79 3643.33,121.46 3710,121.46 3710,54.79 3643.33,54.79 ; 3656.67,68.12 3656.67,108.12 3696.67,108.12 3696.67,68.12 3656.67,68.12 ; 3943.33,88.12 3976.67,121.46 4010,88.12 3976.67,54.79 3943.33,88.12 ; 4093.33,54.79 4093.33,121.46 4160,88.12 4093.33,54.79 ; 4106.67,68.12 4106.67,108.12 4146.67,88.12 4106.67,68.12 ; 4243.33,54.79 4243.33,121.46 4310,88.12 4243.33,54.79 ; 4393.33,88.12 4410,71.46 4410,54.79 4426.67,71.46 4443.33,54.79 4443.33,71.46 4460,88.12 4443.33,104.79 4443.33,121.46 4426.67,104.79 4410,121.46 4410,104.79 4393.33,88.12 ; 4406.67,88.12 4416.67,78.12 4416.67,68.12 4426.67,78.12 4436.67,68.12 4436.67,78.12 4446.67,88.12 4436.67,98.12 4436.67,108.12 4426.67,98.12 4416.67,108.12 4416.67,98.12 4406.67,88.12 ; 4543.33,54.79 4543.33,121.46 4610,121.46 4610,54.79 4543.33,54.79 ; 4693.33,88.12 4710,71.46 4710,54.79 4726.67,71.46 4743.33,54.79 4743.33,71.46 4760,88.12 4743.33,104.79 4743.33,121.46 4726.67,104.79 4710,121.46 4710,104.79 4693.33,88.12
  lines w15: 2855,545.88 4955,545.88 ; 2855,1145.72 4955,1145.72 ; 2855,2295.38 4955,2295.38 ; 2855,2801.26 4955,2801.26 ; 2855,3535.06 4955,3535.06 ; 2855,5034.61 4955,5034.61 ; 2855,5624.46 4955,5624.46 ; 2855,6370.26 4955,6370.26 ; 2855,7020.08 4955,7020.08 ; 2855,7873.85 4955,7873.85 ; 2855,9207.46 4955,9207.46 ; 3005,-5 3005,10586.06 ; 4805,-5 4805,10586.06 ; 2855,-5 2855,10586.06 4955,10586.06 4955,-5 2855,-5
  text "Hole Tolerance (-)" at 2960,9252.46 h72 r90
  text "Hole Tolerance (+)" at 2960,7918.85 h72 r90
  text "Description" at 2960,7065.08 h72 r90
  text "Template" at 2960,6415.26 h72 r90
  text "c160h80" at 3110,6415.26 h60 r90
  text "(Mixed)" at 3260,6415.26 h60 r90
  text "(Mixed)" at 3410,6415.26 h60 r90
  text "c455h277" at 3560,6415.26 h60 r90
  text "c635h381" at 3710,6415.26 h60 r90
  text "v127h71" at 3860,6415.26 h60 r90
  text "c254h158" at 4010,6415.26 h60 r90
  text "c476h326" at 4160,6415.26 h60 r90
  text "v64h30" at 4310,6415.26 h60 r90
  text "(Mixed)" at 4460,6415.26 h60 r90
  text "v102h51" at 4610,6415.26 h60 r90
  text "c127h76" at 4760,6415.26 h60 r90
  text "Pad Shape" at 2960,5669.46 h72 r90
  text "Rounded" at 3110,5669.46 h60 r90
  text "(Mixed)" at 3260,5669.46 h60 r90
  text "(Mixed)" at 3410,5669.46 h60 r90
  text "Rounded" at 3560,5669.46 h60 r90
  text "Rounded" at 3710,5669.46 h60 r90
  text "Rounded" at 3860,5669.46 h60 r90
  text "Rounded" at 4010,5669.46 h60 r90
  text "Rounded" at 4160,5669.46 h60 r90
  text "Rounded" at 4310,5669.46 h60 r90
  text "(Mixed)" at 4460,5669.46 h60 r90
  text "Rounded" at 4610,5669.46 h60 r90
  text "Rounded" at 4760,5669.46 h60 r90
  text "Via/Pad" at 2960,5079.61 h72 r90
  text "Pad" at 3110,5079.61 h60 r90
  text "Pad" at 3260,5079.61 h60 r90
  text "Pad" at 3410,5079.61 h60 r90
  text "Pad" at 3560,5079.61 h60 r90
  text "Pad" at 3710,5079.61 h60 r90
  text "Via" at 3860,5079.61 h60 r90
  text "Pad" at 4010,5079.61 h60 r90
  text "Pad" at 4160,5079.61 h60 r90
  text "Via" at 4310,5079.61 h60 r90
  text "Pad" at 4460,5079.61 h60 r90
  text "Via" at 4610,5079.61 h60 r90
  text "Pad" at 4760,5079.61 h60 r90
  text "Drill Layer Pair" at 2960,3580.06 h72 r90
  text "Top Layer - Bottom Layer" at 3110,3580.06 h60 r90
  text "Top Layer - Bottom Layer" at 3260,3580.06 h60 r90
  text "Top Layer - Bottom Layer" at 3410,3580.06 h60 r90
  text "Top Layer - Bottom Layer" at 3560,3580.06 h60 r90
  text "Top Layer - Bottom Layer" at 3710,3580.06 h60 r90
  text "Top Layer - Bottom Layer" at 3860,3580.06 h60 r90
  text "Top Layer - Bottom Layer" at 4010,3580.06 h60 r90
  text "Top Layer - Bottom Layer" at 4160,3580.06 h60 r90
  text "Top Layer - Bottom Layer" at 4310,3580.06 h60 r90
  text "Top Layer - Bottom Layer" at 4460,3580.06 h60 r90
  text "Top Layer - Bottom Layer" at 4610,3580.06 h60 r90
  text "Top Layer - Bottom Layer" at 4760,3580.06 h60 r90
  text "Hole Type" at 2960,2846.26 h72 r90
  text "Round" at 3110,2846.26 h60 r90
  text "Round" at 3260,2846.26 h60 r90
  text "Round" at 3410,2846.26 h60 r90
  text "Round" at 3560,2846.26 h60 r90
  text "Round" at 3710,2846.26 h60 r90
  text "Round" at 3860,2846.26 h60 r90
  text "Round" at 4010,2846.26 h60 r90
  text "Round" at 4160,2846.26 h60 r90
  text "Round" at 4310,2846.26 h60 r90
  text "Round" at 4460,2846.26 h60 r90
  text "Round" at 4610,2846.26 h60 r90
  text "Round" at 4760,2846.26 h60 r90
  text "Plated" at 2960,2340.38 h72 r90
  text "PTH" at 3110,2340.38 h60 r90
  text "PTH" at 3260,2340.38 h60 r90
  text "PTH" at 3410,2340.38 h60 r90
  text "PTH" at 3560,2340.38 h60 r90
  text "PTH" at 3710,2340.38 h60 r90
  text "PTH" at 3860,2340.38 h60 r90
  text "PTH" at 4010,2340.38 h60 r90
  text "PTH" at 4160,2340.38 h60 r90
  text "PTH" at 4310,2340.38 h60 r90
  text "PTH" at 4460,2340.38 h60 r90
  text "PTH" at 4610,2340.38 h60 r90
  text "PTH" at 4760,2340.38 h60 r90
  text "Hole Size" at 2960,1190.72 h72 r90
  text "0.800mm (31.50mil)" at 3110,1190.72 h60 r90
  text "1.020mm (40.16mil)" at 3260,1190.72 h60 r90
  text "1.750mm (68.90mil)" at 3410,1190.72 h60 r90
  text "2.770mm (109.06mil)" at 3560,1190.72 h60 r90
  text "3.810mm (150.00mil)" at 3710,1190.72 h60 r90
  text "0.711mm (28.00mil)" at 3860,1190.72 h60 r90
  text "1.580mm (62.21mil)" at 4010,1190.72 h60 r90
  text "3.260mm (128.35mil)" at 4160,1190.72 h60 r90
  text "0.305mm (12.00mil)" at 4310,1190.72 h60 r90
  text "1.090mm (42.91mil)" at 4460,1190.72 h60 r90
  text "0.508mm (20.00mil)" at 4610,1190.72 h60 r90
  text "0.762mm (30.00mil)" at 4760,1190.72 h60 r90
  text "Count" at 2960,590.88 h72 r90
  text "2" at 3110,590.88 h60 r90
  text "4" at 3260,590.88 h60 r90
  text "4" at 3410,590.88 h60 r90
  text "4" at 3560,590.88 h60 r90
  text "4" at 3710,590.88 h60 r90
  text "5" at 3860,590.88 h60 r90
  text "7" at 4010,590.88 h60 r90
  text "8" at 4160,590.88 h60 r90
  text "30" at 4310,590.88 h60 r90
  text "36" at 4460,590.88 h60 r90
  text "134" at 4610,590.88 h60 r90
  text "136" at 4760,590.88 h60 r90
  text "374 Total" at 4910,590.88 h60 r90
  text "Symbol" at 2960,85 h72 r90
